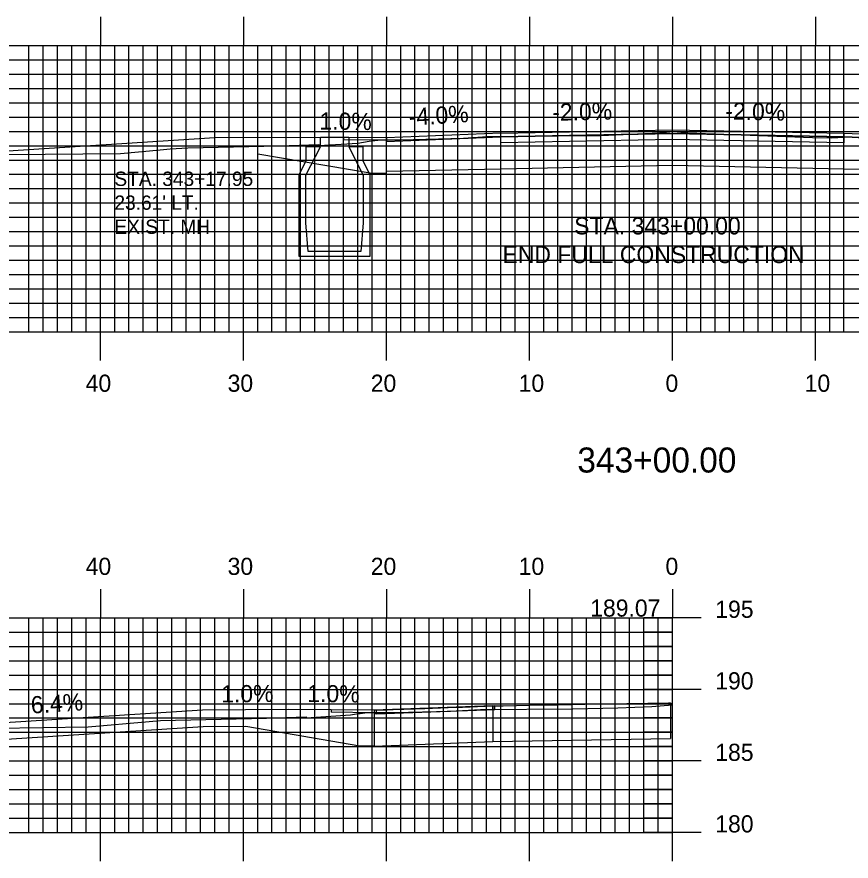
# Model space of a CAD drawing. Extents: x 1825147 to 1825490, y 442591 to 442811.
# Drawn here: x 1825266.5 to 1825324.9, y 442651.7 to 442710.7 of the extents above; entities that cross this region are included whole.
import ezdxf

# ---------------------------------------------------------------- set-up
doc = ezdxf.new("R2010")
doc.units = 0
for name, color, linetype in [('ANNOTATION', 7, 'Continuous'), ('D_Drainage_Culvert', 7, 'Continuous'), ('D_Roadway_Centerline', 7, 'Continuous'), ('D_Roadway_Centerline_Text', 7, 'Continuous'), ('D_Roadway_Edge_Shoulder', 7, 'Continuous'), ('D_Roadway_Edge_TW', 7, 'Continuous'), ('D_Roadway_FinishedGrade', 7, 'Continuous'), ('D_Roadway_Pavement', 7, 'Continuous'), ('D_Roadway_SubGrade', 7, 'Continuous'), ('D_Text_Monospaced', 7, 'Continuous'), ('H_V ANNOTATION', 7, 'Continuous'), ('MAJOR', 7, 'Continuous'), ('MINOR', 7, 'Continuous'), ('S_Roadway_Centerline', 7, 'Continuous'), ('S_Utilities_UG_MH_Unknown', 7, 'Continuous')]:
    doc.layers.add(name, color=color, linetype=linetype)

msp = doc.modelspace()

# ---------------------------------------------------------------- linework, layer by layer
at = {"layer": 'ANNOTATION'}
for points in [[(1825289.361, 442702.243), (1825289.361, 442702.076)], [(1825292.361, 442702.213), (1825292.361, 442702.046), (1825289.361, 442702.076)], [(1825288.511, 442662.232), (1825288.511, 442662.065)], [(1825291.511, 442662.202), (1825291.511, 442662.035), (1825288.511, 442662.065)]]:
    msp.add_lwpolyline(points, dxfattribs=at)
at = {"layer": 'D_Drainage_Culvert'}
msp.add_line((1825291.511, 442662.202), (1825291.511, 442659.702), dxfattribs=at)
at = {"layer": 'D_Roadway_Centerline'}
msp.add_lwpolyline([(1825291.511, 442662.202), (1825291.511, 442662.202), (1825292.418, 442662.236), (1825292.84, 442662.252), (1825295.046, 442662.334), (1825296.689, 442662.395), (1825297.674, 442662.432), (1825299.796, 442662.511), (1825300.362, 442662.521), (1825300.537, 442662.525), (1825303.301, 442662.574), (1825304.386, 442662.594), (1825306.239, 442662.627), (1825308.235, 442662.663), (1825309.178, 442662.68), (1825312.084, 442662.733), (1825312.117, 442662.733), (1825312.222, 442662.735)], dxfattribs=at)
at = {"layer": 'D_Roadway_Edge_Shoulder'}
for points in [[(1825300.361, 442702.533), (1825292.361, 442702.213), (1825292.361, 442701.963), (1825300.361, 442702.283)], [(1825324.361, 442702.533), (1825332.361, 442702.213), (1825332.361, 442701.963), (1825324.361, 442702.283)], [(1825299.796, 442662.511), (1825291.511, 442662.202), (1825291.511, 442661.952), (1825299.796, 442662.261)], [(1825299.934, 442662.514), (1825291.65, 442662.204), (1825291.65, 442661.954), (1825299.934, 442662.264)]]:
    msp.add_lwpolyline(points, close=True, dxfattribs=at)
at = {"layer": 'D_Roadway_Edge_TW'}
msp.add_lwpolyline([(1825300.361, 442702.283), (1825300.361, 442702.533), (1825312.361, 442702.773), (1825324.361, 442702.533), (1825324.361, 442702.283), (1825312.361, 442702.523)], close=True, dxfattribs=at)
at = {"layer": 'D_Roadway_FinishedGrade'}
for p, q in [((1825291.361, 442699.713), (1825283.383, 442701.076)), ((1825292.361, 442699.713), (1825291.361, 442699.713)), ((1825312.222, 442662.735), (1825312.222, 442660.235)), ((1825299.796, 442662.511), (1825299.796, 442660.011)), ((1825290.511, 442659.702), (1825282.533, 442661.065)), ((1825291.511, 442659.702), (1825290.511, 442659.702))]:
    msp.add_line(p, q, dxfattribs=at)
for points in [[(1825291.511, 442662.202), (1825285.511, 442662.262), (1825279.511, 442662.202), (1825259.511, 442660.922)], [(1825291.511, 442662.202), (1825291.511, 442659.702), (1825299.796, 442660.011), (1825312.222, 442660.235)], [(1825282.533, 442661.065), (1825279.554, 442661.036), (1825259.586, 442659.758)]]:
    msp.add_lwpolyline(points, dxfattribs=at)
at = {"layer": 'D_Roadway_Pavement'}
msp.add_lwpolyline([(1825300.361, 442701.866), (1825300.361, 442702.283), (1825312.361, 442702.523), (1825324.361, 442702.283), (1825324.361, 442701.866), (1825312.361, 442702.106)], close=True, dxfattribs=at)
at = {"layer": 'D_Roadway_SubGrade'}
for p, q in [((1825280.361, 442702.213), (1825261.589, 442701.019)), ((1825283.383, 442701.076), (1825283.383, 442702.243))]:
    msp.add_line(p, q, dxfattribs=at)
msp.add_lwpolyline([(1825292.361, 442702.213), (1825283.383, 442702.243), (1825280.361, 442702.213)], dxfattribs=at)
msp.add_lwpolyline([(1825300.361, 442700.033), (1825292.361, 442699.873), (1825292.361, 442702.213), (1825292.361, 442701.963), (1825300.361, 442702.283), (1825312.361, 442702.523), (1825324.361, 442702.283), (1825332.361, 442701.963), (1825332.361, 442702.213), (1825332.361, 442699.873), (1825324.361, 442700.033), (1825312.361, 442700.273)], close=True, dxfattribs=at)
at = {"layer": 'MAJOR'}
for p, q in [((1825272.361, 442710.669), (1825272.361, 442708.665)), ((1825282.361, 442710.669), (1825282.361, 442708.665)), ((1825292.361, 442710.669), (1825292.361, 442708.665)), ((1825302.361, 442710.669), (1825302.361, 442708.665)), ((1825312.361, 442710.669), (1825312.361, 442708.665)), ((1825322.361, 442710.669), (1825322.361, 442708.665)), ((1825172.361, 442708.665), (1825452.361, 442708.665)), ((1825172.361, 442708.665), (1825452.361, 442708.665)), ((1825172.361, 442708.665), (1825452.361, 442708.665)), ((1825272.361, 442688.665), (1825272.361, 442708.665)), ((1825272.361, 442688.665), (1825272.361, 442708.665)), ((1825282.361, 442688.665), (1825282.361, 442708.665)), ((1825282.361, 442688.665), (1825282.361, 442708.665)), ((1825292.361, 442688.665), (1825292.361, 442708.665)), ((1825292.361, 442688.665), (1825292.361, 442708.665)), ((1825302.361, 442688.665), (1825302.361, 442708.665)), ((1825302.361, 442688.665), (1825302.361, 442708.665)), ((1825312.361, 442688.665), (1825312.361, 442708.665)), ((1825312.361, 442688.665), (1825312.361, 442708.665)), ((1825322.361, 442688.665), (1825322.361, 442708.665)), ((1825322.361, 442688.665), (1825322.361, 442708.665)), ((1825172.361, 442703.665), (1825452.361, 442703.665)), ((1825172.361, 442703.665), (1825452.361, 442703.665)), ((1825172.361, 442698.665), (1825452.361, 442698.665)), ((1825172.361, 442698.665), (1825452.361, 442698.665)), ((1825172.361, 442693.665), (1825452.361, 442693.665)), ((1825172.361, 442693.665), (1825452.361, 442693.665)), ((1825172.361, 442688.665), (1825452.361, 442688.665)), ((1825172.361, 442688.665), (1825452.361, 442688.665)), ((1825172.361, 442688.665), (1825452.361, 442688.665)), ((1825272.361, 442686.661), (1825272.361, 442688.665)), ((1825282.361, 442686.661), (1825282.361, 442688.665)), ((1825292.361, 442686.661), (1825292.361, 442688.665)), ((1825302.361, 442686.661), (1825302.361, 442688.665)), ((1825312.361, 442686.661), (1825312.361, 442688.665)), ((1825322.361, 442686.661), (1825322.361, 442688.665)), ((1825272.361, 442670.669), (1825272.361, 442668.665)), ((1825282.361, 442670.669), (1825282.361, 442668.665)), ((1825292.361, 442670.669), (1825292.361, 442668.665)), ((1825302.361, 442670.669), (1825302.361, 442668.665)), ((1825312.361, 442670.669), (1825312.361, 442668.665)), ((1825172.361, 442668.665), (1825312.361, 442668.665)), ((1825172.361, 442668.665), (1825312.361, 442668.665)), ((1825272.361, 442653.665), (1825272.361, 442668.665)), ((1825282.361, 442653.665), (1825282.361, 442668.665)), ((1825292.361, 442653.665), (1825292.361, 442668.665)), ((1825302.361, 442653.665), (1825302.361, 442668.665)), ((1825314.365, 442668.665), (1825310.357, 442668.665)), ((1825312.361, 442653.665), (1825312.361, 442668.665)), ((1825312.361, 442653.665), (1825312.361, 442668.665)), ((1825172.361, 442663.665), (1825312.361, 442663.665)), ((1825314.365, 442663.665), (1825310.357, 442663.665)), ((1825172.361, 442658.665), (1825312.361, 442658.665)), ((1825314.365, 442658.665), (1825310.357, 442658.665)), ((1825172.361, 442653.665), (1825312.361, 442653.665)), ((1825172.361, 442653.665), (1825312.361, 442653.665)), ((1825272.361, 442651.661), (1825272.361, 442653.665)), ((1825282.361, 442651.661), (1825282.361, 442653.665)), ((1825292.361, 442651.661), (1825292.361, 442653.665)), ((1825302.361, 442651.661), (1825302.361, 442653.665)), ((1825314.365, 442653.665), (1825310.357, 442653.665)), ((1825312.361, 442651.661), (1825312.361, 442653.665))]:
    msp.add_line(p, q, dxfattribs=at)
at = {"layer": 'MINOR'}
for p, q in [((1825267.361, 442688.665), (1825267.361, 442708.665)), ((1825267.361, 442688.665), (1825267.361, 442708.665)), ((1825268.361, 442688.665), (1825268.361, 442708.665)), ((1825268.361, 442688.665), (1825268.361, 442708.665)), ((1825269.361, 442688.665), (1825269.361, 442708.665)), ((1825269.361, 442688.665), (1825269.361, 442708.665)), ((1825270.361, 442688.665), (1825270.361, 442708.665)), ((1825270.361, 442688.665), (1825270.361, 442708.665)), ((1825271.361, 442688.665), (1825271.361, 442708.665)), ((1825271.361, 442688.665), (1825271.361, 442708.665)), ((1825273.361, 442688.665), (1825273.361, 442708.665)), ((1825273.361, 442688.665), (1825273.361, 442708.665)), ((1825274.361, 442688.665), (1825274.361, 442708.665)), ((1825274.361, 442688.665), (1825274.361, 442708.665)), ((1825275.361, 442688.665), (1825275.361, 442708.665)), ((1825275.361, 442688.665), (1825275.361, 442708.665)), ((1825276.361, 442688.665), (1825276.361, 442708.665)), ((1825276.361, 442688.665), (1825276.361, 442708.665)), ((1825277.361, 442688.665), (1825277.361, 442708.665)), ((1825277.361, 442688.665), (1825277.361, 442708.665)), ((1825278.361, 442688.665), (1825278.361, 442708.665)), ((1825278.361, 442688.665), (1825278.361, 442708.665)), ((1825279.361, 442688.665), (1825279.361, 442708.665)), ((1825279.361, 442688.665), (1825279.361, 442708.665)), ((1825280.361, 442688.665), (1825280.361, 442708.665)), ((1825280.361, 442688.665), (1825280.361, 442708.665)), ((1825281.361, 442688.665), (1825281.361, 442708.665)), ((1825281.361, 442688.665), (1825281.361, 442708.665)), ((1825283.361, 442688.665), (1825283.361, 442708.665)), ((1825283.361, 442688.665), (1825283.361, 442708.665)), ((1825284.361, 442688.665), (1825284.361, 442708.665)), ((1825284.361, 442688.665), (1825284.361, 442708.665)), ((1825285.361, 442688.665), (1825285.361, 442708.665)), ((1825285.361, 442688.665), (1825285.361, 442708.665)), ((1825286.361, 442688.665), (1825286.361, 442708.665)), ((1825286.361, 442688.665), (1825286.361, 442708.665)), ((1825287.361, 442688.665), (1825287.361, 442708.665)), ((1825287.361, 442688.665), (1825287.361, 442708.665)), ((1825288.361, 442688.665), (1825288.361, 442708.665)), ((1825288.361, 442688.665), (1825288.361, 442708.665)), ((1825289.361, 442688.665), (1825289.361, 442708.665)), ((1825289.361, 442688.665), (1825289.361, 442708.665)), ((1825290.361, 442688.665), (1825290.361, 442708.665)), ((1825290.361, 442688.665), (1825290.361, 442708.665)), ((1825291.361, 442688.665), (1825291.361, 442708.665)), ((1825291.361, 442688.665), (1825291.361, 442708.665)), ((1825293.361, 442688.665), (1825293.361, 442708.665)), ((1825293.361, 442688.665), (1825293.361, 442708.665)), ((1825294.361, 442688.665), (1825294.361, 442708.665)), ((1825294.361, 442688.665), (1825294.361, 442708.665)), ((1825295.361, 442688.665), (1825295.361, 442708.665)), ((1825295.361, 442688.665), (1825295.361, 442708.665)), ((1825296.361, 442688.665), (1825296.361, 442708.665)), ((1825296.361, 442688.665), (1825296.361, 442708.665)), ((1825297.361, 442688.665), (1825297.361, 442708.665)), ((1825297.361, 442688.665), (1825297.361, 442708.665)), ((1825298.361, 442688.665), (1825298.361, 442708.665)), ((1825298.361, 442688.665), (1825298.361, 442708.665)), ((1825299.361, 442688.665), (1825299.361, 442708.665)), ((1825299.361, 442688.665), (1825299.361, 442708.665)), ((1825300.361, 442688.665), (1825300.361, 442708.665)), ((1825300.361, 442688.665), (1825300.361, 442708.665)), ((1825301.361, 442688.665), (1825301.361, 442708.665)), ((1825301.361, 442688.665), (1825301.361, 442708.665)), ((1825303.361, 442688.665), (1825303.361, 442708.665)), ((1825303.361, 442688.665), (1825303.361, 442708.665)), ((1825304.361, 442688.665), (1825304.361, 442708.665)), ((1825304.361, 442688.665), (1825304.361, 442708.665)), ((1825305.361, 442688.665), (1825305.361, 442708.665)), ((1825305.361, 442688.665), (1825305.361, 442708.665)), ((1825306.361, 442688.665), (1825306.361, 442708.665)), ((1825306.361, 442688.665), (1825306.361, 442708.665)), ((1825307.361, 442688.665), (1825307.361, 442708.665)), ((1825307.361, 442688.665), (1825307.361, 442708.665)), ((1825308.361, 442688.665), (1825308.361, 442708.665)), ((1825308.361, 442688.665), (1825308.361, 442708.665)), ((1825309.361, 442688.665), (1825309.361, 442708.665)), ((1825309.361, 442688.665), (1825309.361, 442708.665)), ((1825310.361, 442688.665), (1825310.361, 442708.665)), ((1825310.361, 442688.665), (1825310.361, 442708.665)), ((1825311.361, 442688.665), (1825311.361, 442708.665)), ((1825311.361, 442688.665), (1825311.361, 442708.665)), ((1825313.361, 442688.665), (1825313.361, 442708.665)), ((1825313.361, 442688.665), (1825313.361, 442708.665)), ((1825314.361, 442688.665), (1825314.361, 442708.665)), ((1825314.361, 442688.665), (1825314.361, 442708.665)), ((1825315.361, 442688.665), (1825315.361, 442708.665)), ((1825315.361, 442688.665), (1825315.361, 442708.665)), ((1825316.361, 442688.665), (1825316.361, 442708.665)), ((1825316.361, 442688.665), (1825316.361, 442708.665)), ((1825317.361, 442688.665), (1825317.361, 442708.665)), ((1825317.361, 442688.665), (1825317.361, 442708.665)), ((1825318.361, 442688.665), (1825318.361, 442708.665)), ((1825318.361, 442688.665), (1825318.361, 442708.665)), ((1825319.361, 442688.665), (1825319.361, 442708.665)), ((1825319.361, 442688.665), (1825319.361, 442708.665)), ((1825320.361, 442688.665), (1825320.361, 442708.665)), ((1825320.361, 442688.665), (1825320.361, 442708.665)), ((1825321.361, 442688.665), (1825321.361, 442708.665)), ((1825321.361, 442688.665), (1825321.361, 442708.665)), ((1825323.361, 442688.665), (1825323.361, 442708.665)), ((1825323.361, 442688.665), (1825323.361, 442708.665)), ((1825324.361, 442688.665), (1825324.361, 442708.665)), ((1825324.361, 442688.665), (1825324.361, 442708.665)), ((1825172.361, 442707.665), (1825452.361, 442707.665)), ((1825172.361, 442707.665), (1825452.361, 442707.665)), ((1825172.361, 442706.665), (1825452.361, 442706.665)), ((1825172.361, 442706.665), (1825452.361, 442706.665)), ((1825172.361, 442705.665), (1825452.361, 442705.665)), ((1825172.361, 442705.665), (1825452.361, 442705.665)), ((1825172.361, 442704.665), (1825452.361, 442704.665)), ((1825172.361, 442704.665), (1825452.361, 442704.665)), ((1825172.361, 442702.665), (1825452.361, 442702.665)), ((1825172.361, 442702.665), (1825452.361, 442702.665)), ((1825172.361, 442701.665), (1825452.361, 442701.665)), ((1825172.361, 442701.665), (1825452.361, 442701.665)), ((1825172.361, 442700.665), (1825452.361, 442700.665)), ((1825172.361, 442700.665), (1825452.361, 442700.665)), ((1825172.361, 442699.665), (1825452.361, 442699.665)), ((1825172.361, 442699.665), (1825452.361, 442699.665)), ((1825172.361, 442697.665), (1825452.361, 442697.665)), ((1825172.361, 442697.665), (1825452.361, 442697.665)), ((1825172.361, 442696.665), (1825452.361, 442696.665)), ((1825172.361, 442696.665), (1825452.361, 442696.665)), ((1825172.361, 442695.665), (1825452.361, 442695.665)), ((1825172.361, 442695.665), (1825452.361, 442695.665)), ((1825172.361, 442694.665), (1825452.361, 442694.665)), ((1825172.361, 442694.665), (1825452.361, 442694.665)), ((1825172.361, 442692.665), (1825452.361, 442692.665)), ((1825172.361, 442692.665), (1825452.361, 442692.665)), ((1825172.361, 442691.665), (1825452.361, 442691.665)), ((1825172.361, 442691.665), (1825452.361, 442691.665)), ((1825172.361, 442690.665), (1825452.361, 442690.665)), ((1825172.361, 442690.665), (1825452.361, 442690.665)), ((1825172.361, 442689.665), (1825452.361, 442689.665)), ((1825172.361, 442689.665), (1825452.361, 442689.665)), ((1825267.361, 442653.665), (1825267.361, 442668.665)), ((1825268.361, 442653.665), (1825268.361, 442668.665)), ((1825269.361, 442653.665), (1825269.361, 442668.665)), ((1825270.361, 442653.665), (1825270.361, 442668.665)), ((1825271.361, 442653.665), (1825271.361, 442668.665)), ((1825273.361, 442653.665), (1825273.361, 442668.665)), ((1825274.361, 442653.665), (1825274.361, 442668.665)), ((1825275.361, 442653.665), (1825275.361, 442668.665)), ((1825276.361, 442653.665), (1825276.361, 442668.665)), ((1825277.361, 442653.665), (1825277.361, 442668.665)), ((1825278.361, 442653.665), (1825278.361, 442668.665)), ((1825279.361, 442653.665), (1825279.361, 442668.665)), ((1825280.361, 442653.665), (1825280.361, 442668.665)), ((1825281.361, 442653.665), (1825281.361, 442668.665)), ((1825283.361, 442653.665), (1825283.361, 442668.665)), ((1825284.361, 442653.665), (1825284.361, 442668.665)), ((1825285.361, 442653.665), (1825285.361, 442668.665)), ((1825286.361, 442653.665), (1825286.361, 442668.665)), ((1825287.361, 442653.665), (1825287.361, 442668.665)), ((1825288.361, 442653.665), (1825288.361, 442668.665)), ((1825289.361, 442653.665), (1825289.361, 442668.665)), ((1825290.361, 442653.665), (1825290.361, 442668.665)), ((1825291.361, 442653.665), (1825291.361, 442668.665)), ((1825293.361, 442653.665), (1825293.361, 442668.665)), ((1825294.361, 442653.665), (1825294.361, 442668.665)), ((1825295.361, 442653.665), (1825295.361, 442668.665)), ((1825296.361, 442653.665), (1825296.361, 442668.665)), ((1825297.361, 442653.665), (1825297.361, 442668.665)), ((1825298.361, 442653.665), (1825298.361, 442668.665)), ((1825299.361, 442653.665), (1825299.361, 442668.665)), ((1825300.361, 442653.665), (1825300.361, 442668.665)), ((1825301.361, 442653.665), (1825301.361, 442668.665)), ((1825303.361, 442653.665), (1825303.361, 442668.665)), ((1825304.361, 442653.665), (1825304.361, 442668.665)), ((1825305.361, 442653.665), (1825305.361, 442668.665)), ((1825306.361, 442653.665), (1825306.361, 442668.665)), ((1825307.361, 442653.665), (1825307.361, 442668.665)), ((1825308.361, 442653.665), (1825308.361, 442668.665)), ((1825309.361, 442653.665), (1825309.361, 442668.665)), ((1825310.361, 442653.665), (1825310.361, 442668.665)), ((1825311.361, 442653.665), (1825311.361, 442668.665)), ((1825172.361, 442667.665), (1825312.361, 442667.665)), ((1825312.361, 442667.665), (1825310.357, 442667.665)), ((1825172.361, 442666.665), (1825312.361, 442666.665)), ((1825312.361, 442666.665), (1825310.357, 442666.665)), ((1825172.361, 442665.665), (1825312.361, 442665.665)), ((1825312.361, 442665.665), (1825310.357, 442665.665)), ((1825172.361, 442664.665), (1825312.361, 442664.665)), ((1825312.361, 442664.665), (1825310.357, 442664.665)), ((1825172.361, 442662.665), (1825312.361, 442662.665)), ((1825312.361, 442662.665), (1825310.357, 442662.665)), ((1825172.361, 442661.665), (1825312.361, 442661.665)), ((1825312.361, 442661.665), (1825310.357, 442661.665)), ((1825172.361, 442660.665), (1825312.361, 442660.665)), ((1825312.361, 442660.665), (1825310.357, 442660.665)), ((1825172.361, 442659.665), (1825312.361, 442659.665)), ((1825312.361, 442659.665), (1825310.357, 442659.665)), ((1825172.361, 442657.665), (1825312.361, 442657.665)), ((1825312.361, 442657.665), (1825310.357, 442657.665)), ((1825172.361, 442656.665), (1825312.361, 442656.665)), ((1825312.361, 442656.665), (1825310.357, 442656.665)), ((1825172.361, 442655.665), (1825312.361, 442655.665)), ((1825312.361, 442655.665), (1825310.357, 442655.665)), ((1825172.361, 442654.665), (1825312.361, 442654.665)), ((1825312.361, 442654.665), (1825310.357, 442654.665))]:
    msp.add_line(p, q, dxfattribs=at)
at = {"layer": 'S_Roadway_Centerline'}
for points in [[(1825260.563, 442701.01), (1825273.772, 442701.125), (1825276.553, 442701.386), (1825277.244, 442701.458), (1825278.487, 442701.518), (1825284.86, 442701.647), (1825287.642, 442701.751), (1825287.645, 442701.677), (1825290.372, 442701.854), (1825291.159, 442701.993), (1825291.336, 442702.002), (1825291.773, 442702.059), (1825291.861, 442702.067), (1825293.383, 442702.071), (1825297.763, 442702.188), (1825299.416, 442702.297), (1825306.81, 442702.37), (1825307.392, 442702.382), (1825311.467, 442702.557), (1825312.434, 442702.649), (1825313.443, 442702.568), (1825322.158, 442702.229), (1825323.512, 442702.213), (1825324.751, 442702.284), (1825326.279, 442702.169)], [(1825265.091, 442660.95), (1825271.513, 442661.04), (1825275.773, 442661.427), (1825276.033, 442661.453), (1825276.57, 442661.479), (1825283.974, 442661.645), (1825286.754, 442661.756), (1825286.757, 442661.68), (1825289.853, 442661.882), (1825290.411, 442661.976), (1825290.528, 442661.981), (1825291.025, 442662.042), (1825291.126, 442662.05), (1825292.927, 442662.05), (1825296.855, 442662.137), (1825298.948, 442662.266), (1825305.403, 442662.314), (1825308.547, 442662.369), (1825310.93, 442662.461), (1825312.361, 442662.59)]]:
    msp.add_lwpolyline(points, dxfattribs=at)
at = {"layer": 'S_Utilities_UG_MH_Unknown'}
for p, q in [((1825286.729, 442699.597), (1825287.746, 442701.598)), ((1825287.746, 442701.598), (1825286.729, 442701.598)), ((1825286.729, 442701.598), (1825286.729, 442700.614)), ((1825290.732, 442701.598), (1825289.747, 442701.598)), ((1825289.747, 442701.598), (1825290.732, 442699.597)), ((1825290.732, 442700.614), (1825290.732, 442701.598)), ((1825286.729, 442700.614), (1825286.237, 442699.597)), ((1825291.224, 442699.597), (1825290.732, 442700.614)), ((1825286.237, 442699.597), (1825286.237, 442693.954)), ((1825286.729, 442696.283), (1825286.729, 442699.597)), ((1825290.732, 442699.597), (1825290.732, 442696.283)), ((1825291.224, 442693.954), (1825291.224, 442699.597)), ((1825286.893, 442694.282), (1825286.729, 442696.283)), ((1825290.732, 442696.283), (1825290.568, 442694.282)), ((1825286.237, 442693.954), (1825291.224, 442693.954)), ((1825290.568, 442694.282), (1825286.893, 442694.282))]:
    msp.add_line(p, q, dxfattribs=at)
msp.add_lwpolyline([(1825287.254, 442701.64), (1825287.746, 442701.64), (1825287.746, 442702.263), (1825289.747, 442702.263), (1825289.747, 442701.64), (1825290.24, 442701.64)], dxfattribs=at)

# ---------------------------------------------------------------- texts
at = {"layer": 'ANNOTATION'}
for s, rotation, p in [('-2.0%', 1.14576, (1825303.967, 442703.405)), ('-2.0%', 358.85424, (1825316.047, 442703.499)), ('1.0%', 359.42672, (1825287.676, 442702.793)), ('-4.0%', 3.36949, (1825293.958, 442703.069)), ('1.0%', 0.57294, (1825280.815, 442662.749)), ('1.0%', 359.42672, (1825286.826, 442662.783)), ('6.4%', 3.66194, (1825267.533, 442661.97))]:
    msp.add_text(s, height=1.2, rotation=rotation, dxfattribs=at).set_placement(p)
for s, p in [('STA. 343+00.00', (1825305.497, 442695.465)), ('END FULL CONSTRUCTION', (1825300.482, 442693.461))]:
    msp.add_text(s, height=1.2, dxfattribs=at).set_placement(p)
at = {"layer": 'D_Roadway_Centerline'}
for s, p in [('C', (1825312.356, 442702.773)), ('L', (1825312.361, 442702.765))]:
    msp.add_text(s, height=0.0146, dxfattribs=at).set_placement(p)
at = {"layer": 'D_Roadway_Centerline_Text'}
msp.add_text('189.07', height=1.2, dxfattribs=at).set_placement((1825306.615, 442668.749))
at = {"layer": 'D_Text_Monospaced'}
for s, height, p in [('STA. 343+17.95', 0.99996, (1825273.344, 442698.853)), ("23.61' LT.", 1, (1825273.344, 442697.185)), ('EXIST. MH', 1, (1825273.344, 442695.505))]:
    msp.add_text(s, height=height, dxfattribs=at).set_placement(p)
at = {"layer": 'H_V ANNOTATION'}
for s, height, p in [('40', 1.2, (1825271.333, 442684.465)), ('30', 1.2, (1825281.258, 442684.465)), ('20', 1.2, (1825291.269, 442684.465)), ('10', 1.2, (1825301.612, 442684.465)), ('0', 1.2, (1825311.879, 442684.465)), ('10', 1.2, (1825321.612, 442684.465)), ('343+00.00', 1.75, (1825305.713, 442678.821)), ('40', 1.2, (1825271.333, 442671.665)), ('30', 1.2, (1825281.258, 442671.665)), ('20', 1.2, (1825291.269, 442671.665)), ('10', 1.2, (1825301.612, 442671.665)), ('0', 1.2, (1825311.879, 442671.665)), ('195', 1.2, (1825315.361, 442668.665)), ('190', 1.2, (1825315.361, 442663.665)), ('185', 1.2, (1825315.361, 442658.665)), ('180', 1.2, (1825315.361, 442653.665))]:
    msp.add_text(s, height=height, dxfattribs=at).set_placement(p)
at = {"layer": 'S_Roadway_Centerline'}
for s, p in [('L', (1825312.425, 442702.642)), ('C', (1825312.429, 442702.649))]:
    msp.add_text(s, height=0.0146, dxfattribs=at).set_placement(p)

doc.saveas('drawing.dxf')
